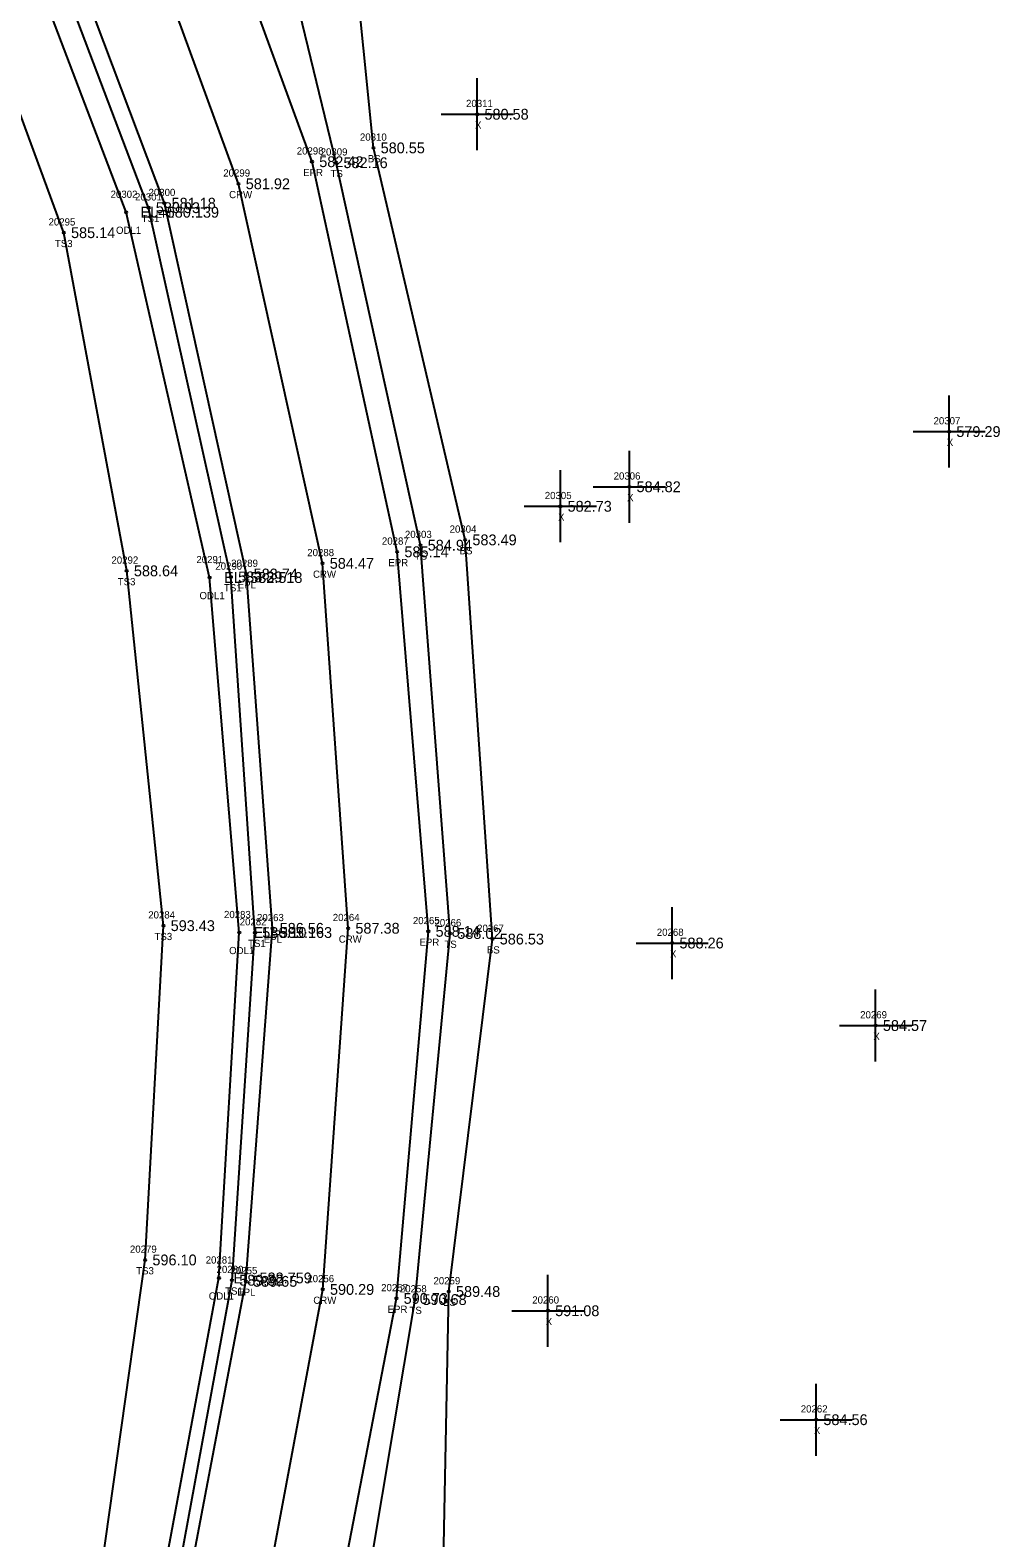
# Model space of a CAD drawing. Extents: x 1695443 to 1696344, y 1087542 to 1090645.
# Drawn here: x 1696004.9 to 1696139.4, y 1088621.2 to 1088830.4 of the extents above; entities that cross this region are included whole.
import ezdxf

# ---------------------------------------------------------------- set-up
doc = ezdxf.new("R2010")
doc.units = 0
for name, color, linetype in [('RD_DTM_BkLn1', 7, 'Continuous'), ('RD_DTM_BkLn2', 7, 'Continuous'), ('RD_DTM_BkLn_txCode', 7, 'Continuous'), ('RD_EX_H2O', 7, 'Continuous'), ('RD_EX_H2O_txCode', 7, 'Continuous'), ('RD_EX_Misc', 7, 'Continuous'), ('RD_EX_Misc_txCode', 7, 'Continuous'), ('RD_EX_Road', 7, 'Continuous'), ('RD_EX_Road_txCode', 7, 'Continuous'), ('RD_EX_TX_H2O_ELEV', 7, 'Continuous'), ('RD_EX_TX_Misc_ELEV', 7, 'Continuous'), ('RD_EX_TX_Road_ELEV', 7, 'Continuous'), ('RD_HC_Survey_ELEV', 7, 'Continuous'), ('RD_HC_Survey_txCode', 7, 'Continuous'), ('RD_SMD_Locator', 7, 'Continuous')]:
    doc.layers.add(name, color=color, linetype=linetype)

msp = doc.modelspace()

# ---------------------------------------------------------------- linework, layer by layer
at = {"layer": 'RD_DTM_BkLn1'}
msp.add_lwpolyline([(1695869.23, 1087563.38), (1695882.71, 1087666.87), (1695895.39, 1087768.85), (1695908.05, 1087871.3), (1695919.71, 1087974.19), (1695925.35, 1088026.13), (1695931.27, 1088077.73), (1695937.88, 1088128.75), (1695945.4, 1088182.97), (1695952.48, 1088232.38), (1695961.74, 1088286.36), (1695971.36, 1088336.92), (1695982.91, 1088390.82), (1696009.16, 1088497.22), (1696035.45, 1088601.7), (1696045.5, 1088655.66), (1696049.03, 1088705.78), (1696045.47, 1088756.42), (1696033.82, 1088809.1), (1696016.78, 1088855.71), (1695990.89, 1088906.17), (1695964.41, 1088947.39), (1695931.21, 1088992.88)], dxfattribs=at)
at = {"layer": 'RD_DTM_BkLn2'}
for points in [[(1695957.06, 1088113.83), (1695958.4, 1088124.86), (1695969.72, 1088175.5), (1695984.45, 1088233.12), (1695986.34, 1088280.33), (1695995.02, 1088332.7), (1696009.2, 1088386.54), (1696038.3, 1088489.24), (1696061.78, 1088594.39), (1696062.98, 1088655.37), (1696069.05, 1088704.28), (1696065.26, 1088759.68), (1696052.53, 1088814.08), (1696046.96, 1088869.93), (1696016.66, 1088919.05), (1695997.75, 1088967.45), (1695944.59, 1089014.67), (1695937.23, 1089009.08)], [(1696049.23, 1088599.85), (1696058.32, 1088654.25), (1696063.16, 1088705.06), (1696059.06, 1088758.94), (1696047.37, 1088812.02), (1696038.37, 1088849.01), (1696038.12, 1088863.45), (1696009.85, 1088916.52), (1695988.88, 1088960.6), (1695962.07, 1088998.83), (1695953.25, 1089002.55), (1695942.32, 1089000.92)], [(1695916.78, 1088084), (1695925.73, 1088132.37), (1695932.55, 1088186.85), (1695940.12, 1088233.39), (1695949.48, 1088288.14), (1695959.7, 1088339.01), (1695971.73, 1088394.21), (1695997.36, 1088500.21), (1696023.08, 1088603.25), (1696032.92, 1088656.94), (1696036.1, 1088705.18), (1696032.76, 1088754.54), (1696021.34, 1088805.78), (1696004.42, 1088850.43), (1695979.2, 1088899.43), (1695947.85, 1088934.07), (1695935.29, 1088941.42), (1695930.1, 1088962.13), (1695923.44, 1088976.06), (1695917.46, 1088980.5), (1695920.03, 1088983.92)], [(1695811.33, 1088056.44), (1695848.8, 1088075.62), (1695896.28, 1088098.14), (1695916.78, 1088084), (1695919.84, 1088133.52), (1695923.64, 1088187.73), (1695930.8, 1088232.96), (1695939.58, 1088289.44), (1695949.3, 1088339.9), (1695960.86, 1088397.31), (1695988.69, 1088500.86), (1696013.19, 1088605.35), (1696020.87, 1088659.75), (1696023.4, 1088706.14), (1696018.3, 1088755.38), (1696009.58, 1088802.31), (1695993.24, 1088846.7), (1695969.88, 1088894.03), (1695962.8, 1088910.68)]]:
    msp.add_lwpolyline(points, dxfattribs=at)
at = {"layer": 'RD_EX_H2O'}
msp.add_lwpolyline([(1695916.78, 1088084), (1695923.72, 1088132.78), (1695929.91, 1088186.51), (1695936.75, 1088234.45), (1695946.8, 1088289.18), (1695957.47, 1088339.74), (1695969.14, 1088394.61), (1695994.85, 1088500.6), (1696021.07, 1088603.21), (1696031.1, 1088657.25), (1696033.92, 1088705.19), (1696029.81, 1088754.45), (1696018.23, 1088805.15), (1696001.4, 1088849.48), (1695973.58, 1088895.84), (1695962.8, 1088910.68)], dxfattribs=at)
at = {"layer": 'RD_EX_Misc'}
for p, q in [((1696066.93, 1088813.75), (1696066.93, 1088823.75)), ((1696061.93, 1088818.75), (1696071.93, 1088818.75)), ((1696132.39, 1088769.71), (1696132.39, 1088779.71)), ((1696127.39, 1088774.71), (1696137.39, 1088774.71)), ((1696088.03, 1088762.05), (1696088.03, 1088772.05)), ((1696078.46, 1088759.34), (1696078.46, 1088769.34)), ((1696083.03, 1088767.05), (1696093.03, 1088767.05)), ((1696073.46, 1088764.34), (1696083.46, 1088764.34)), ((1696093.98, 1088698.73), (1696093.98, 1088708.73)), ((1696088.98, 1088703.73), (1696098.98, 1088703.73)), ((1696122.2, 1088687.28), (1696122.2, 1088697.28)), ((1696117.2, 1088692.28), (1696127.2, 1088692.28)), ((1696076.74, 1088647.7), (1696076.74, 1088657.7)), ((1696071.74, 1088652.7), (1696081.74, 1088652.7)), ((1696113.95, 1088632.58), (1696113.95, 1088642.58)), ((1696108.95, 1088637.58), (1696118.95, 1088637.58))]:
    msp.add_line(p, q, dxfattribs=at)
at = {"layer": 'RD_EX_Road'}
for points in [[(1695879.87, 1087561.29), (1695893.33, 1087665.71), (1695905.96, 1087767.16), (1695918.66, 1087869.54), (1695930.87, 1087972.82), (1695936.26, 1088023.68), (1695942.14, 1088076.32), (1695948.07, 1088128.17), (1695955.04, 1088181.4), (1695962.88, 1088230.72), (1695971.68, 1088284.64), (1695982.02, 1088336.12), (1695993.28, 1088388.48), (1696018.75, 1088494.48), (1696045.23, 1088599.95), (1696055.72, 1088654.41), (1696060.15, 1088705.35), (1696055.83, 1088758.02), (1696044.01, 1088812.16), (1696026.4, 1088860.33), (1696000.41, 1088911.48), (1695972.46, 1088953.82), (1695939.48, 1088998.73), (1695931.21, 1088992.88)], [(1696024.81, 1088603.86), (1696034.83, 1088656.78), (1696038.52, 1088705.77), (1696034.91, 1088754.94), (1696023.53, 1088806.4), (1696006.7, 1088851.13), (1695981.74, 1088901.12), (1695956.26, 1088941.69), (1695923.39, 1088986.66), (1695931.21, 1088992.88)]]:
    msp.add_lwpolyline(points, dxfattribs=at)
at = {"layer": 'RD_SMD_Locator'}
for centre in [(1696066.93, 1088818.75), (1696052.53, 1088814.08), (1696044.01, 1088812.16), (1696047.37, 1088812.02), (1696033.82, 1088809.1), (1696021.34, 1088805.78), (1696023.53, 1088806.4), (1696018.23, 1088805.15), (1696009.58, 1088802.31), (1696132.39, 1088774.71), (1696088.03, 1088767.05), (1696078.46, 1088764.34), (1696065.26, 1088759.68), (1696055.83, 1088758.02), (1696059.06, 1088758.94), (1696018.3, 1088755.38), (1696045.47, 1088756.42), (1696029.81, 1088754.45), (1696032.76, 1088754.54), (1696034.91, 1088754.94), (1696023.4, 1088706.14), (1696033.92, 1088705.19), (1696036.1, 1088705.18), (1696038.52, 1088705.77), (1696049.03, 1088705.78), (1696060.15, 1088705.35), (1696063.16, 1088705.06), (1696069.05, 1088704.28), (1696093.98, 1088703.73), (1696122.2, 1088692.28), (1696020.87, 1088659.75), (1696031.1, 1088657.25), (1696032.92, 1088656.94), (1696034.83, 1088656.78), (1696045.5, 1088655.66), (1696062.98, 1088655.37), (1696055.72, 1088654.41), (1696058.32, 1088654.25), (1696076.74, 1088652.7), (1696113.95, 1088637.58)]:
    msp.add_circle(centre, 0.15, dxfattribs=at)

# ---------------------------------------------------------------- texts
at = {"layer": 'RD_DTM_BkLn_txCode'}
for s, p in [('20310', (1696050.66, 1088815.08)), ('20309', (1696045.21, 1088813.02)), ('BS', (1696051.75, 1088812.08)), ('TS', (1696046.58, 1088810.02)), ('20301', (1696019.46, 1088806.78)), ('20295', (1696007.46, 1088803.31)), ('TS1', (1696020.38, 1088803.78)), ('TS3', (1696008.34, 1088800.31)), ('20304', (1696063.1, 1088760.68)), ('20303', (1696056.9, 1088759.94)), ('TS', (1696058.26, 1088756.94)), ('BS', (1696064.48, 1088757.68)), ('20292', (1696016.19, 1088756.38)), ('20290', (1696030.6, 1088755.54)), ('TS3', (1696017.06, 1088753.38)), ('TS1', (1696031.8, 1088752.54)), ('20284', (1696021.29, 1088707.14)), ('TS3', (1696022.16, 1088704.14)), ('20282', (1696033.98, 1088706.18)), ('20266', (1696061, 1088706.06)), ('20267', (1696066.91, 1088705.28)), ('TS1', (1696035.14, 1088703.18)), ('TS', (1696062.37, 1088703.06)), ('BS', (1696068.27, 1088702.28)), ('20279', (1696018.75, 1088660.75)), ('TS3', (1696019.62, 1088657.75)), ('20280', (1696030.77, 1088657.94)), ('20259', (1696060.86, 1088656.37)), ('TS1', (1696031.96, 1088654.94)), ('20258', (1696056.2, 1088655.25)), ('TS', (1696057.53, 1088652.25)), ('BS', (1696062.2, 1088653.37))]:
    msp.add_text(s, height=1, dxfattribs=at).set_placement(p)
at = {"layer": 'RD_EX_H2O_txCode'}
for s, p in [('20302', (1696016.07, 1088807.15)), ('ODL1', (1696016.82, 1088802.15)), ('20291', (1696027.97, 1088756.45)), ('ODL1', (1696028.4, 1088751.45)), ('20283', (1696031.8, 1088707.19)), ('ODL1', (1696032.51, 1088702.19)), ('20281', (1696029.26, 1088659.25)), ('ODL1', (1696029.69, 1088654.25))]:
    msp.add_text(s, height=1, dxfattribs=at).set_placement(p)
at = {"layer": 'RD_EX_Misc_txCode'}
for s, p in [('20311', (1696065.38, 1088819.75)), ('X', (1696066.62, 1088816.75)), ('20307', (1696130.23, 1088775.71)), ('X', (1696132.07, 1088772.71)), ('20306', (1696085.85, 1088768.05)), ('20305', (1696076.3, 1088765.34)), ('X', (1696087.72, 1088765.05)), ('X', (1696078.14, 1088762.34)), ('20268', (1696091.84, 1088704.73)), ('X', (1696093.67, 1088701.73)), ('20269', (1696120.05, 1088693.28)), ('X', (1696121.88, 1088690.28)), ('20260', (1696074.56, 1088653.7)), ('X', (1696076.43, 1088650.7)), ('20262', (1696111.81, 1088638.58)), ('X', (1696113.64, 1088635.58))]:
    msp.add_text(s, height=1, dxfattribs=at).set_placement(p)
at = {"layer": 'RD_EX_Road_txCode'}
for s, p in [('20298', (1696041.89, 1088813.16)), ('EPR', (1696042.78, 1088810.16)), ('20300', (1696021.33, 1088807.4)), ('EPL', (1696022.33, 1088804.4)), ('20287', (1696053.71, 1088759.02)), ('20289', (1696032.79, 1088755.94)), ('EPR', (1696054.6, 1088756.02)), ('EPL', (1696033.7, 1088752.94)), ('20263', (1696036.38, 1088706.77)), ('20265', (1696058, 1088706.35)), ('EPL', (1696037.31, 1088703.77)), ('EPR', (1696058.92, 1088703.35)), ('20255', (1696032.71, 1088657.78)), ('EPL', (1696033.63, 1088654.78)), ('20257', (1696053.6, 1088655.41)), ('EPR', (1696054.49, 1088652.41))]:
    msp.add_text(s, height=1, dxfattribs=at).set_placement(p)
at = {"layer": 'RD_EX_TX_H2O_ELEV'}
for s, p in [('EL=580.139', (1696020.23, 1088804.4)), ('EL=582.518', (1696031.81, 1088753.7)), ('EL=585.163', (1696035.92, 1088704.44)), ('EL=588.759', (1696033.1, 1088656.5))]:
    msp.add_text(s, height=1.5, dxfattribs=at).set_placement(p)
at = {"layer": 'RD_EX_TX_Misc_ELEV'}
for s, p in [('580.58', (1696067.93, 1088818)), ('580.55', (1696053.53, 1088813.33)), ('582.16', (1696048.37, 1088811.27)), ('580.93', (1696022.34, 1088805.03)), ('585.14', (1696010.58, 1088801.56)), ('579.29', (1696133.39, 1088773.96)), ('584.82', (1696089.03, 1088766.3)), ('582.73', (1696079.46, 1088763.59)), ('584.94', (1696060.06, 1088758.19)), ('583.49', (1696066.26, 1088758.93)), ('588.64', (1696019.3, 1088754.63)), ('583.39', (1696033.76, 1088753.79)), ('593.43', (1696024.4, 1088705.39)), ('586.10', (1696037.1, 1088704.43)), ('588.02', (1696064.16, 1088704.31)), ('586.53', (1696070.05, 1088703.53)), ('588.26', (1696094.98, 1088702.98)), ('584.57', (1696123.2, 1088691.53)), ('596.10', (1696021.87, 1088659)), ('589.32', (1696033.92, 1088656.19)), ('590.68', (1696059.32, 1088653.5)), ('589.48', (1696063.98, 1088654.62)), ('591.08', (1696077.74, 1088651.95)), ('584.56', (1696114.95, 1088636.83))]:
    msp.add_text(s, height=1.5, dxfattribs=at).set_placement(p)
at = {"layer": 'RD_EX_TX_Road_ELEV'}
for s, p in [('582.42', (1696045.01, 1088811.41)), ('581.18', (1696024.53, 1088805.65)), ('585.14', (1696056.83, 1088757.27)), ('583.74', (1696035.91, 1088754.19)), ('586.56', (1696039.52, 1088705.02)), ('588.14', (1696061.15, 1088704.6)), ('589.65', (1696035.83, 1088656.03)), ('590.73', (1696056.72, 1088653.66))]:
    msp.add_text(s, height=1.5, dxfattribs=at).set_placement(p)
at = {"layer": 'RD_HC_Survey_ELEV'}
for s, p in [('581.92', (1696034.82, 1088808.35)), ('584.47', (1696046.47, 1088755.67)), ('587.38', (1696050.03, 1088705.03)), ('590.29', (1696046.5, 1088654.91))]:
    msp.add_text(s, height=1.5, dxfattribs=at).set_placement(p)
at = {"layer": 'RD_HC_Survey_txCode'}
for s, p in [('20299', (1696031.7, 1088810.1)), ('CRW', (1696032.51, 1088807.1)), ('20288', (1696043.35, 1088757.42)), ('CRW', (1696044.15, 1088754.42)), ('20264', (1696046.89, 1088706.78)), ('CRW', (1696047.72, 1088703.78)), ('20256', (1696043.36, 1088656.66)), ('CRW', (1696044.19, 1088653.66))]:
    msp.add_text(s, height=1, dxfattribs=at).set_placement(p)

doc.saveas('drawing.dxf')
